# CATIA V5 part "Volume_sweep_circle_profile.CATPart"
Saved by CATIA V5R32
Part number: Part1
Bounding box of the stored display mesh (mm): x -183.601 to 0, y -90.736 to 90.736, z -90.733 to 90.733
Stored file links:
  D:\PROJECTS\Project 2022\CATIA V5 6R 2022\Resources\Part Files\c17_catia_v6_6r2022_prt\Volume_sweep_circle_profile.CATPart
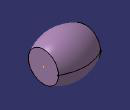
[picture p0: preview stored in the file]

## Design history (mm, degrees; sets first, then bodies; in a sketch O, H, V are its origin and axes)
Set1
  Sketch1 on xy-plane, origin (0, 0, 0), H (1, 0, 0), V (0, 1, 0)
    line L1 (0, 0) -> (-183.1008, 0)
    horizontal: L1 H
  Sketch2 on xy-plane, origin (0, 0, 0), H (1, 0, 0), V (0, 1, 0)
    spline S1 through (0, 65.5148) (-89.6654, 90.7245) (-183.6013, 65.5148)
    point P1 (0, 65.5148)
    coincidence: P1 V
  Sweep1: type Circle, Guide Sketch1, Reference Sketch2, Radius 55
Body1 (main body)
